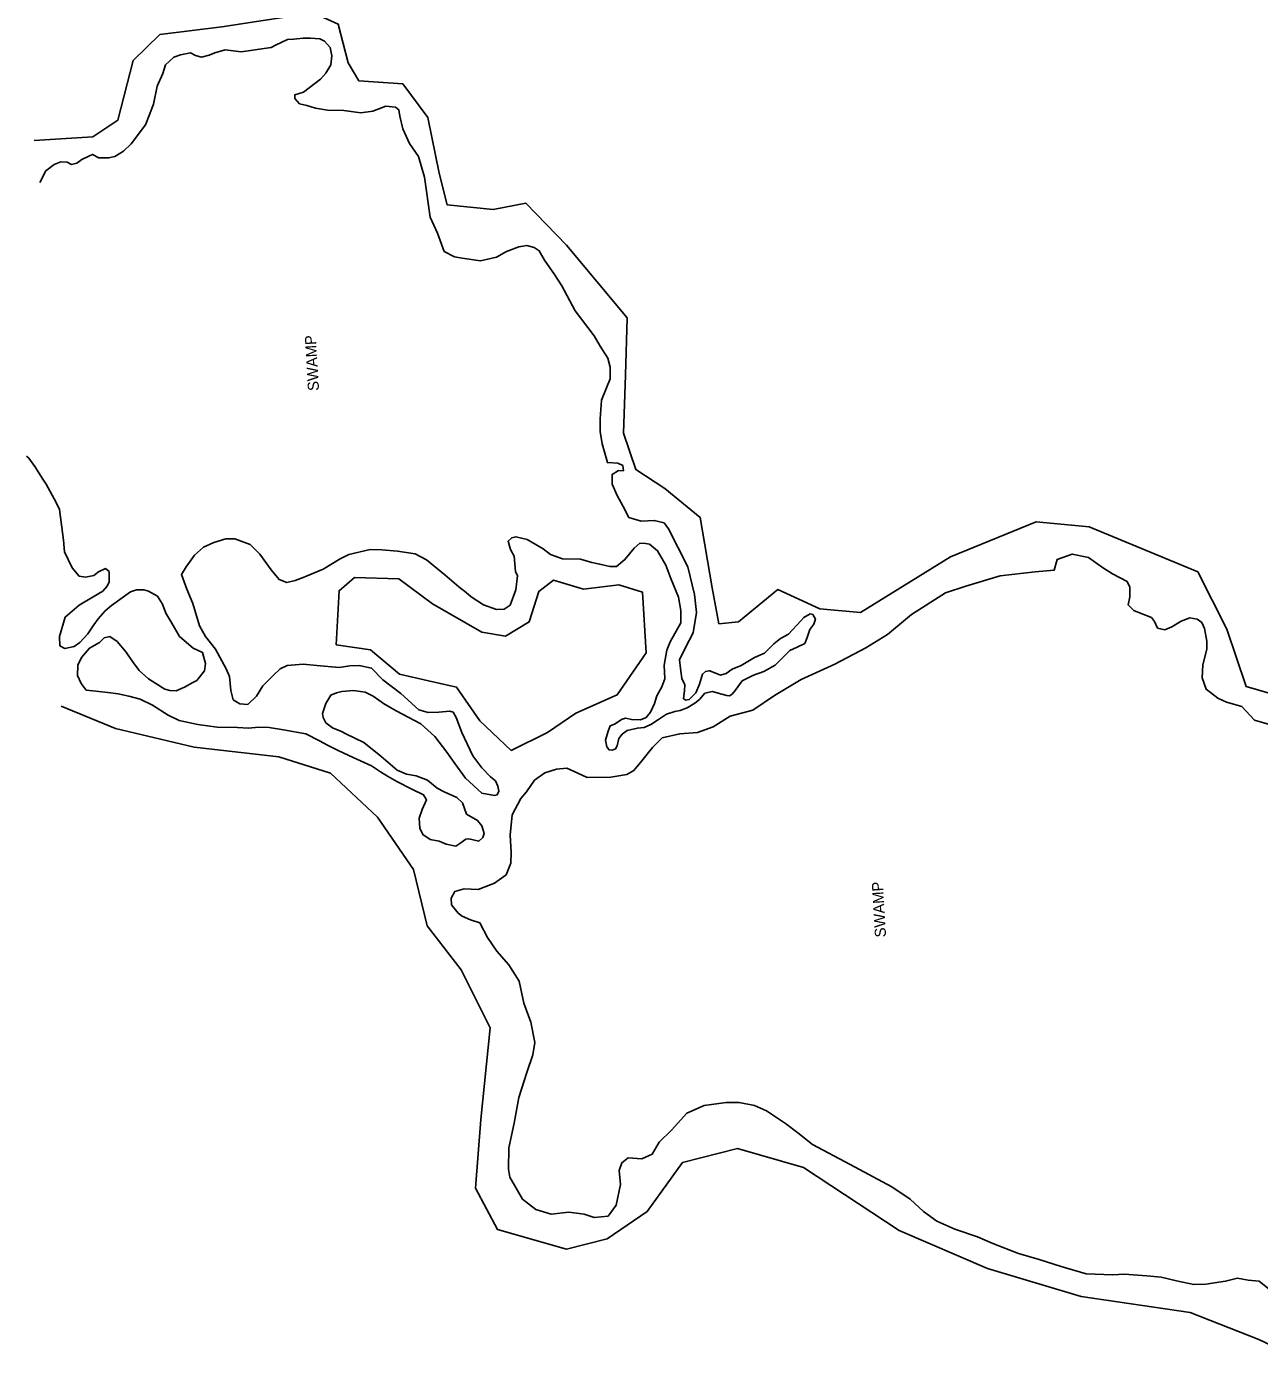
# Model space of a CAD drawing. Extents: x 2030130 to 2036320, y 723205 to 762423.
# Drawn here: x 2033435.3 to 2033881.6, y 736024.8 to 736506.9 of the extents above; entities that cross this region are included whole.
import ezdxf

# ---------------------------------------------------------------- set-up
doc = ezdxf.new("R2010")
doc.units = 0
for name, color, linetype in [('Draft_Station Tics Major', 7, 'Continuous'), ('Prop Alignment Horizontal', 7, 'Continuous'), ('Prop Alignment Vertical', 7, 'Continuous')]:
    doc.layers.add(name, color=color, linetype=linetype)

msp = doc.modelspace()

# ---------------------------------------------------------------- linework, layer by layer
at = {"layer": 'Draft_Station Tics Major'}
for points in [[(2033571.43, 736486.26), (2033555.5, 736487.36), (2033551.67, 736493.83), (2033548.08, 736507.8), (2033538.98, 736511.94), (2033505.92, 736506.85), (2033483.52, 736504.11), (2033473.79, 736494.62), (2033468.28, 736473.06), (2033459.23, 736467), (2033438.03, 736465.76)], [(2033921.01, 736255.26), (2033876.79, 736268.04), (2033869.77, 736288.85), (2033859.28, 736309.59), (2033819.99, 736325.86), (2033800.81, 736327.64), (2033769.81, 736314.98), (2033737.23, 736294.87), (2033722.45, 736296.12), (2033707.29, 736303.15), (2033693.06, 736291.49), (2033685.92, 736290.76), (2033683.46, 736303.73), (2033679.09, 736329.27), (2033666.34, 736339.68), (2033655.79, 736346.56), (2033651.41, 736359.79), (2033652.09, 736380.73), (2033652.76, 736401.49), (2033630.72, 736427.79), (2033616.02, 736443.08), (2033604.21, 736440.76), (2033587.52, 736442.46), (2033584.62, 736453.9), (2033580.47, 736474.04), (2033571.43, 736486.26)], [(2033547.36, 736283.12), (2033548.38, 736302.71), (2033553.92, 736307.54), (2033570.06, 736307.01), (2033582.27, 736297.96), (2033600.03, 736287.77), (2033608.64, 736286.34), (2033617.27, 736291.44), (2033620.7, 736302.49), (2033626.03, 736306.55), (2033636.89, 736303.31), (2033649.63, 736304.82), (2033658.21, 736302.24), (2033659.61, 736280.26), (2033649.11, 736265.02), (2033634.09, 736258.39), (2033623.86, 736251.41), (2033610.76, 736244.91), (2033599.37, 736255.66), (2033590.92, 736267.86), (2033580.79, 736270.12), (2033570.29, 736272.57), (2033559.8, 736281.38), (2033547.36, 736283.12)], [(2033447.76, 736260.95), (2033467.5, 736252.81), (2033495.95, 736246.12), (2033526.62, 736242.63), (2033545.28, 736236.64), (2033562.27, 736220.7), (2033575.31, 736201.81), (2033580.23, 736181.45), (2033592.61, 736165.47), (2033603.09, 736144.54), (2033599.71, 736111.37), (2033597.74, 736086.43), (2033605.73, 736071.55), (2033630.7, 736064.39), (2033645.44, 736068.15), (2033660, 736078.06), (2033672.69, 736095.74), (2033692.67, 736100.86), (2033716.49, 736093.93), (2033751.15, 736071.08), (2033783.22, 736057.34), (2033817.13, 736047.2), (2033856.58, 736041.5), (2033881.46, 736031.66), (2033895.86, 736024.84)]]:
    msp.add_lwpolyline(points, dxfattribs=at)
at = {"layer": 'Prop Alignment Horizontal'}
for points in [[(2033440.05, 736450.48), (2033442.17, 736454.76), (2033445.27, 736457.03), (2033447.67, 736458), (2033449.91, 736457.93), (2033451.46, 736457.09), (2033453.45, 736457.55), (2033455.21, 736458.81), (2033458.02, 736460.17), (2033459.09, 736460.66), (2033461.42, 736459.4), (2033464.97, 736459.42), (2033467.23, 736459.87), (2033470.32, 736461.88), (2033473.17, 736464.56), (2033478.27, 736471.37), (2033479.69, 736474.75), (2033481.15, 736478.92), (2033482.54, 736485.33), (2033484.53, 736490), (2033485.56, 736493.13), (2033488.55, 736495.93), (2033490.94, 736496.78), (2033494.65, 736497.45), (2033496.47, 736496.47), (2033498.55, 736495.87), (2033501.34, 736496.57), (2033503.35, 736497.43), (2033507.2, 736498.49), (2033512.97, 736497.78), (2033523.83, 736499.4), (2033525.43, 736500.27), (2033529.71, 736502.24), (2033531.96, 736502.43), (2033535.39, 736502.72), (2033538.03, 736502.76), (2033541.44, 736502.52), (2033543.13, 736501.67), (2033545.16, 736499.37), (2033545.72, 736496.32), (2033545.36, 736493.17), (2033543.54, 736490.07), (2033541.63, 736487.89), (2033535.55, 736483.22), (2033532.36, 736482.27), (2033532.32, 736480.95), (2033534.1, 736479.05), (2033536.71, 736478.44), (2033539.84, 736477.41), (2033544.17, 736476.75), (2033550.09, 736476.56), (2033556.25, 736475.7), (2033560.62, 736476.35), (2033565.29, 736478.17), (2033568.83, 736477.79), (2033569.99, 736476.83), (2033570.44, 736474.58), (2033571.48, 736469.94), (2033573.94, 736464.59), (2033577.21, 736459.87), (2033579.34, 736452.43), (2033581.37, 736438), (2033584.08, 736432.12), (2033586.5, 736425.59), (2033590.13, 736423.63), (2033593.01, 736423.14), (2033599.56, 736422.14), (2033605.41, 736423.53), (2033609.03, 736425.52), (2033613.43, 736427.22), (2033616.34, 736427.65), (2033619.08, 736427.04), (2033620.89, 736425.79), (2033622.76, 736422.44), (2033626.41, 736417.19), (2033629.04, 736413.15), (2033633.88, 736404.04), (2033640.7, 736394.99), (2033642.95, 736391.23), (2033645.71, 736386.93), (2033646.53, 736383.61), (2033646.52, 736379.39), (2033645.23, 736376.14), (2033643.38, 736371.72), (2033642.9, 736365.02), (2033642.88, 736360.41), (2033643.65, 736355.91), (2033645.54, 736349.13), (2033649.35, 736348.87), (2033651.17, 736348.03), (2033651.37, 736346.17), (2033649.53, 736346.23), (2033647.25, 736344.86), (2033647.26, 736341.3), (2033649.11, 736337.16), (2033651.22, 736333.27), (2033653.33, 736329.25), (2033657.76, 736327.92), (2033662.51, 736328.16), (2033666.04, 736327.26), (2033667.68, 736325.1)], [(2033499.64, 736273.79), (2033500.02, 736276.39), (2033498.96, 736280.37), (2033495.58, 736281.93), (2033490.59, 736286.18), (2033487.84, 736291.01), (2033485.72, 736294.63), (2033484.51, 736297.83), (2033482.63, 736300.79), (2033479.39, 736302.61), (2033477.7, 736303.06), (2033475.06, 736303.01), (2033472.93, 736302.29), (2033466.05, 736297.38), (2033463.75, 736295.47), (2033461.16, 736292.53), (2033459.64, 736290.34), (2033457.42, 736287.12), (2033454.56, 736284.05), (2033452.53, 736282.54), (2033449.09, 736281.86), (2033447.28, 736282.84), (2033447.12, 736286.13), (2033449.19, 736293.18), (2033454.33, 736297.49), (2033459.31, 736300.49), (2033462.8, 736302.62), (2033464.44, 736304.41), (2033465.15, 736305.97), (2033465.13, 736309.66), (2033463.85, 736310.75), (2033461.31, 736309.52), (2033459.56, 736308.26), (2033456.64, 736307.69), (2033454.28, 736308.03), (2033451.74, 736311.01), (2033449.03, 736316.76), (2033448.64, 736320.99), (2033447.16, 736332.1), (2033445.92, 736334.64), (2033442.32, 736341.35), (2033441.19, 736343.1), (2033438.18, 736347.67), (2033436.04, 736350.77), (2033435.27, 736351.45)], [(2033667.68, 736325.1), (2033671.03, 736318.54), (2033674.62, 736311.44), (2033677.06, 736301.35), (2033677.77, 736294.87), (2033676.61, 736287.54), (2033673.8, 736282.23), (2033671.68, 736277.69), (2033671.99, 736274.59)], [(2033666.29, 736270.83), (2033666.09, 736275.76), (2033667.05, 736281.26), (2033668.21, 736284.25), (2033672.12, 736291.11), (2033672.13, 736295.58), (2033671.23, 736300.35), (2033668.55, 736307.16), (2033666.73, 736311.96), (2033663.74, 736317.19), (2033660.79, 736319.53), (2033659.35, 736319.84), (2033657.24, 736319.91), (2033655.21, 736318.13), (2033651.91, 736314.02), (2033648.8, 736311.49), (2033646.43, 736311.56), (2033642.77, 736312.34), (2033639.89, 736312.96), (2033635.85, 736314.14), (2033629.27, 736314.22), (2033624.97, 736315.81), (2033622.27, 736317.88), (2033616.45, 736321.22), (2033612.4, 736322.28), (2033610.94, 736321.93), (2033609.58, 736320.66), (2033610.41, 736317.6), (2033611.78, 736315.19), (2033612.26, 736309.64), (2033613, 736308.17), (2033612.44, 736303.05), (2033610.28, 736297.45), (2033608.13, 736296.07), (2033605.36, 736295.9), (2033600.67, 736297.63), (2033596.16, 736300.54), (2033594.36, 736302.05), (2033591.8, 736304.11), (2033586.67, 736308.49), (2033580, 736313.97), (2033575.98, 736316.08), (2033569.56, 736317.08), (2033563.91, 736317.52), (2033559.7, 736317.66), (2033551.87, 736315.81), (2033548.79, 736314.33), (2033542.61, 736310.57), (2033535.4, 736307.51), (2033532.47, 736306.42), (2033529.42, 736305.73), (2033526.68, 736306.74), (2033523.77, 736310.26), (2033519.73, 736315.92), (2033516.16, 736319.46), (2033510.69, 736321.48), (2033507.4, 736321.46), (2033503.01, 736320.15), (2033499.27, 736318.56), (2033496.02, 736315.64), (2033492.98, 736311.39), (2033491.31, 736308.55), (2033493.25, 736303.35), (2033495.45, 736298.14), (2033497.82, 736290.03), (2033500.07, 736286.13), (2033503.61, 736281.54), (2033507.46, 736274.44), (2033508.69, 736271.63), (2033509.18, 736266.61), (2033510, 736263.29), (2033512.45, 736261.76), (2033515.34, 736261.54), (2033518.47, 736264.6), (2033520.83, 736268.34), (2033524.51, 736272.04), (2033527.09, 736274.46), (2033529.63, 736275.69), (2033535.44, 736276.17), (2033540.3, 736275.61), (2033548.44, 736274.95), (2033552.28, 736275.49), (2033555.71, 736275.64), (2033560.15, 736274.71), (2033564.23, 736270.49), (2033570.79, 736265.54), (2033577.32, 736259.66)], [(2033698.22, 736259.44), (2033706.04, 736264.85), (2033715.71, 736270.6), (2033727.87, 736276.13), (2033739.13, 736282.09), (2033746.92, 736286.84), (2033755.59, 736294.07), (2033767.96, 736301.97), (2033775.28, 736304.36), (2033787.79, 736308.17), (2033800.48, 736309.61), (2033807.34, 736310.18), (2033808.39, 736314.09), (2033813.86, 736316.02), (2033819.74, 736314.78), (2033824.76, 736311.19), (2033828.38, 736308.84), (2033833.68, 736306.03), (2033834.67, 736304.02), (2033834.69, 736300.47), (2033834.07, 736297.59), (2033836.11, 736295.55), (2033838.19, 736294.69), (2033842.49, 736293.1), (2033843.62, 736291.62), (2033844.73, 736289.21), (2033847.35, 736288.6), (2033849.88, 736289.7), (2033853.24, 736291.7), (2033856.44, 736292.91), (2033859.06, 736292.43), (2033860.73, 736291.19), (2033861.72, 736289.06), (2033862.62, 736284.42), (2033862.53, 736281.52), (2033861.16, 736275.9), (2033860.88, 736271.17), (2033862.32, 736267.04), (2033866.57, 736263.87), (2033869.68, 736262.45), (2033875.29, 736260.82), (2033879.88, 736255.93), (2033897.36, 736250.76)], [(2033666.29, 736270.83), (2033665.28, 736267.96), (2033663.46, 736264.67), (2033662.58, 736261.87), (2033661.1, 736258.82), (2033659.52, 736256.83), (2033657.52, 736255.97), (2033654.23, 736256.15), (2033652.21, 736256.61), (2033650.88, 736256.25), (2033648.06, 736254.37), (2033646.52, 736253.83), (2033645.87, 736251.94), (2033644.91, 736248.68), (2033645.36, 736246.23), (2033646.18, 736245.09), (2033647.23, 736244.99), (2033648.49, 736245.47), (2033649.05, 736246.57), (2033649.67, 736249.19), (2033650.84, 736250.79), (2033652.72, 736252.11), (2033656.44, 736252.98), (2033658.88, 736253.23), (2033661.28, 736254.34), (2033664.1, 736256.09), (2033667, 736258.1), (2033669.99, 736258.99), (2033671.91, 736259.33), (2033674.44, 736260.3), (2033677.19, 736261.98), (2033678.88, 736263.38), (2033680.87, 736265.62), (2033683.58, 736266.25), (2033686.52, 736265.43), (2033688.8, 736264.77), (2033689.79, 736264.67), (2033690.66, 736265.23), (2033691.76, 736266.58), (2033694.37, 736270.12), (2033698.45, 736272.16), (2033702.18, 736273.48), (2033706.34, 736275.78), (2033708.24, 736277.76), (2033711.58, 736281.14), (2033714.31, 736282.31), (2033716.99, 736283.6), (2033717.91, 736285.81), (2033718.8, 736288.68), (2033720.24, 736290.6), (2033720.83, 736292.49), (2033719.96, 736294.1), (2033718.92, 736294.4), (2033716.7, 736293.09), (2033715.54, 736291.81), (2033711.11, 736286.95), (2033708.16, 736285.47), (2033705.86, 736283.5), (2033702.46, 736280.12), (2033698.86, 736278.53), (2033693.96, 736275.72), (2033690.76, 736274.31), (2033688.6, 736272.8), (2033686.54, 736272.15), (2033682.64, 736273.72), (2033682.44, 736273.73), (2033681.05, 736273.44), (2033679.97, 736272.49), (2033678.93, 736268.91), (2033677.52, 736265.79), (2033675.2, 736263.3), (2033673.81, 736263.08), (2033673.04, 736263.7), (2033673.46, 736266.45), (2033673.53, 736268.69), (2033672.48, 736270.96), (2033671.99, 736274.59)], [(2033511.57, 736253.2), (2033504.27, 736253.37), (2033497.26, 736254.25), (2033490.53, 736255.78), (2033486.51, 736257.69), (2033480.9, 736261.3), (2033476.43, 736263.48), (2033472.32, 736264.53), (2033468.4, 736265.39), (2033464.73, 736265.9), (2033459.29, 736266.47), (2033456.86, 736266.75), (2033454.96, 736269.11), (2033453.74, 736272.05), (2033453.8, 736275.8), (2033455.14, 736278.58), (2033458.01, 736281.98), (2033461.63, 736284.03), (2033463.33, 736285.62), (2033465.39, 736286.15), (2033468.09, 736284.35), (2033471.26, 736280.5), (2033473.65, 736277.13), (2033475.98, 736273.89), (2033479.37, 736270.82), (2033482.01, 736269.09), (2033485.3, 736267.08), (2033487.06, 736266.56), (2033489.37, 736266.55), (2033492.43, 736267.77), (2033495.45, 736269.45), (2033496.86, 736270.26), (2033499.64, 736273.79)], [(2033577.32, 736259.66), (2033580.71, 736258.63), (2033584.53, 736258.77), (2033588.5, 736259.17), (2033589.67, 736258.74), (2033590.79, 736256.86), (2033592.86, 736251.39), (2033596.8, 736242.96), (2033600.08, 736238.64), (2033603.27, 736235.38), (2033605.07, 736233.87), (2033605.93, 736232), (2033606.26, 736230.15), (2033605.69, 736228.85), (2033604.63, 736228.62), (2033600.05, 736229.42), (2033594.17, 736234.88), (2033590.25, 736240.15), (2033587.36, 736244.32), (2033583.06, 736249.99), (2033577.94, 736254.51), (2033573.41, 736257.02), (2033569.27, 736259.13), (2033564.87, 736261.65), (2033560.75, 736264.55), (2033557.9, 736265.96), (2033553.57, 736266.62), (2033549.34, 736266.23), (2033547.48, 736265.77), (2033545.35, 736264.91), (2033543.54, 736261.94), (2033542.37, 736258.29), (2033542.59, 736256.84), (2033543.58, 736254.96), (2033546.02, 736253.04), (2033549.27, 736251.75), (2033550.86, 736250.98)], [(2033614.21, 736227.52), (2033616.27, 736229.95), (2033619.17, 736234.21), (2033622.94, 736236.85), (2033627.07, 736238.17), (2033630.9, 736238.44), (2033634.79, 736236.73), (2033638.17, 736235.17), (2033646.73, 736235.29), (2033652.56, 736236.16), (2033655.11, 736237.65), (2033657.99, 736241.12), (2033661.83, 736246), (2033665.37, 736249.44), (2033671.74, 736250.95), (2033678.21, 736251.39), (2033683.81, 736253.45), (2033689.99, 736257.34), (2033698.22, 736259.44)], [(2033548.12, 736244.85), (2033544.24, 736246.77), (2033541.26, 736248.45), (2033536.34, 736250.98), (2033528.22, 736252.43), (2033523.11, 736253.25), (2033519.29, 736253.37), (2033515.59, 736252.97), (2033511.57, 736253.2)], [(2033550.86, 736250.98), (2033557.4, 736247.75), (2033563.5, 736242.88), (2033569.45, 736237.81), (2033572.76, 736236.32), (2033576.3, 736235.68), (2033580.39, 736234.1), (2033583.85, 736231.29), (2033586.44, 736229.89), (2033590.98, 736227.9), (2033593.03, 736225.93), (2033594.47, 736221.87), (2033598.48, 736219.5), (2033600.13, 736217.67), (2033600.89, 736214.88), (2033600.39, 736213.45), (2033598.96, 736212.05), (2033595.37, 736212.89), (2033594.31, 736212.85), (2033592.09, 736211.21), (2033590.68, 736210.27), (2033587.21, 736211.04), (2033584.61, 736212.11), (2033581.41, 736212.68), (2033578.7, 736214.48), (2033577.59, 736216.75), (2033577.38, 736220.38), (2033578.47, 736223.57), (2033580.03, 736227.07), (2033578.97, 736228.88), (2033574.76, 736230.86), (2033569.32, 736233.67), (2033565.96, 736235.62), (2033563.45, 736237.22), (2033560.16, 736239.3), (2033553.48, 736242.34), (2033548.12, 736244.85)], [(2033885.32, 736049.76), (2033881.47, 736052.78), (2033877.53, 736053.17), (2033873.73, 736053.82), (2033869.35, 736052.78), (2033862.21, 736051.69), (2033857.85, 736051.57), (2033851.58, 736052.96), (2033846.09, 736054.19), (2033840.84, 736054.75), (2033832.69, 736055.28), (2033828.59, 736055.02), (2033818.86, 736055.46), (2033809.86, 736058.13), (2033801.91, 736060.62), (2033794.34, 736062.84), (2033785.1, 736066.43), (2033779.52, 736068.85), (2033771.31, 736071.62), (2033764.82, 736074.47), (2033759.93, 736078.05), (2033755.19, 736082.42), (2033748.49, 736086.98), (2033733.47, 736094.97), (2033719.75, 736102.27), (2033714.48, 736106.52), (2033709.98, 736109.83), (2033703.15, 736114.4), (2033698.86, 736116.38), (2033693.24, 736117.48), (2033688.5, 736117.5), (2033680.56, 736116.44), (2033674.28, 736113.62), (2033668.81, 736107.47), (2033664.32, 736103.14), (2033661.81, 736098.74), (2033658.07, 736097.02), (2033653.07, 736097.44), (2033650.78, 736095.67), (2033649.76, 736092.81), (2033650.26, 736087.79), (2033648.7, 736080.33), (2033645.81, 736076.34), (2033640.79, 736075.84), (2033637.13, 736077.02), (2033631.63, 736077.72), (2033625.15, 736077.01), (2033619.67, 736078.77), (2033616.97, 736080.83), (2033614.79, 736082.48), (2033610.17, 736090.4), (2033609.74, 736093.31), (2033609.86, 736101.08), (2033611.73, 736109.98), (2033613.48, 736119.27), (2033616.4, 736128.27), (2033618.59, 736134.78), (2033619.26, 736139.24), (2033617.78, 736146.53), (2033615.24, 736153.46), (2033613.65, 736161.41), (2033609.89, 736167.33), (2033605.57, 736172.21), (2033602.18, 736177.2), (2033599.32, 736182.56), (2033595.93, 736183.59), (2033592.94, 736184.87), (2033591.53, 736185.97), (2033589.13, 736189.08), (2033588.94, 736191.45), (2033590.34, 736193.91), (2033593.66, 736194.86), (2033598.79, 736194.56), (2033604.66, 736196.87), (2033608.84, 736199.9), (2033610.55, 736204.06), (2033610.69, 736208.14), (2033610.36, 736214.21), (2033611.12, 736221.56), (2033614.21, 736227.52)]]:
    msp.add_lwpolyline(points, dxfattribs=at)

# ---------------------------------------------------------------- texts
at = {"layer": 'Prop Alignment Vertical'}
for p in [(2033541.16, 736375.19), (2033746.45, 736177.36)]:
    msp.add_text('SWAMP', height=4, rotation=93.4083, dxfattribs=at).set_placement(p)

doc.saveas('drawing.dxf')
